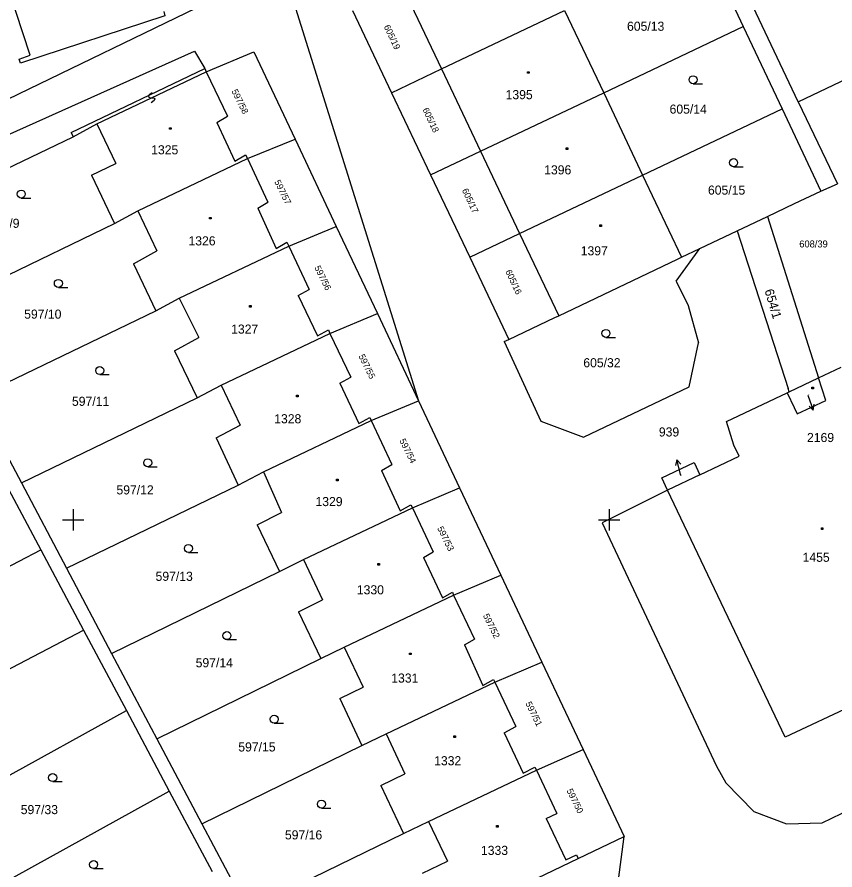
# Model space of a CAD drawing. Extents: x -493648 to -493033, y -1127718 to -1127026.
# Drawn here: x -493205.2 to -493128.9, y -1127182.7 to -1127103.1 of the extents above; entities that cross this region are included whole.
import ezdxf

# ---------------------------------------------------------------- set-up
doc = ezdxf.new("R2010")
doc.units = 0
doc.layers.add('katastrální mapa', color=7, linetype='Continuous')
doc.layers.add('síť', color=7, linetype='Continuous')

msp = doc.modelspace()

# ---------------------------------------------------------------- linework, layer by layer
at = {"layer": 'katastrální mapa'}
for p, q in [((-493189.34, -1127070.04), (-493167.78, -1127138.87)), ((-493141.11, -1127096.24), (-493137.49, -1127103.93)), ((-493169.28, -1127100.21), (-493165.63, -1127107.89)), ((-493220.46, -1127117.66), (-493186.04, -1127100.98)), ((-493132.35, -1127110.95), (-493136.84, -1127101.5)), ((-493173.95, -1127102.43), (-493170.3, -1127110.11)), ((-493165.63, -1127107.89), (-493154.16, -1127102.44)), ((-493154.16, -1127102.44), (-493150.51, -1127110.12)), ((-493132.35, -1127110.95), (-493116.05, -1127103.21)), ((-493150.51, -1127110.12), (-493137.49, -1127103.93)), ((-493137.49, -1127103.93), (-493133.87, -1127111.62)), ((-493218.92, -1127119.76), (-493188.68, -1127106.24)), ((-493188.68, -1127106.24), (-493187.73, -1127107.85)), ((-493187.59, -1127108.15), (-493183.14, -1127106.31)), ((-493183.14, -1127106.31), (-493179.3, -1127114.45)), ((-493200.2, -1127113.82), (-493187.73, -1127107.85)), ((-493197.79, -1127113.01), (-493187.59, -1127108.15)), ((-493187.73, -1127107.85), (-493187.59, -1127108.15)), ((-493187.59, -1127108.15), (-493185.62, -1127112.31)), ((-493170.3, -1127110.11), (-493165.63, -1127107.89)), ((-493165.63, -1127107.89), (-493161.99, -1127115.57)), ((-493157.61, -1127108.15), (-493157.46, -1127108.15)), ((-493157.61, -1127108.3), (-493157.61, -1127108.15)), ((-493157.46, -1127108.3), (-493157.61, -1127108.3)), ((-493157.46, -1127108.15), (-493157.46, -1127108.3)), ((-493142.17, -1127109.28), (-493141.29, -1127109.28)), ((-493192.93, -1127110.31), (-493192.98, -1127110.44)), ((-493192.98, -1127110.44), (-493192.94, -1127110.53)), ((-493192.94, -1127110.53), (-493192.8, -1127110.58)), ((-493192.64, -1127110.11), (-493192.93, -1127110.31)), ((-493192.8, -1127110.58), (-493192.58, -1127110.58)), ((-493192.45, -1127110.85), (-493192.74, -1127111.05)), ((-493192.58, -1127110.58), (-493192.44, -1127110.63)), ((-493192.4, -1127110.72), (-493192.45, -1127110.85)), ((-493192.44, -1127110.63), (-493192.4, -1127110.72)), ((-493170.3, -1127110.11), (-493166.66, -1127117.79)), ((-493161.99, -1127115.57), (-493150.51, -1127110.12)), ((-493150.51, -1127110.12), (-493146.88, -1127117.8)), ((-493146.88, -1127117.8), (-493133.87, -1127111.62)), ((-493133.87, -1127111.62), (-493130.25, -1127119.31)), ((-493132.35, -1127110.95), (-493128.69, -1127118.63)), ((-493186.6, -1127112.9), (-493185.62, -1127112.31)), ((-493200.01, -1127114.22), (-493197.79, -1127113.01)), ((-493197.79, -1127113.01), (-493196.03, -1127116.73)), ((-493186.6, -1127112.9), (-493184.91, -1127116.52)), ((-493200.2, -1127113.82), (-493200.01, -1127114.22)), ((-493191.02, -1127113.38), (-493190.87, -1127113.38)), ((-493191.02, -1127113.53), (-493191.02, -1127113.38)), ((-493190.87, -1127113.53), (-493191.02, -1127113.53)), ((-493190.87, -1127113.38), (-493190.87, -1127113.53)), ((-493217.49, -1127122.64), (-493200.01, -1127114.22)), ((-493183.75, -1127116.27), (-493179.3, -1127114.45)), ((-493179.3, -1127114.45), (-493175.46, -1127122.59)), ((-493166.66, -1127117.79), (-493161.99, -1127115.57)), ((-493161.99, -1127115.57), (-493158.35, -1127123.25)), ((-493154.01, -1127115.26), (-493153.86, -1127115.26)), ((-493154.01, -1127115.41), (-493154.01, -1127115.26)), ((-493153.86, -1127115.41), (-493154.01, -1127115.41)), ((-493153.86, -1127115.26), (-493153.86, -1127115.41)), ((-493193.97, -1127121.13), (-493183.75, -1127116.27)), ((-493184.91, -1127116.52), (-493183.92, -1127115.92)), ((-493183.92, -1127115.92), (-493183.75, -1127116.27)), ((-493183.75, -1127116.27), (-493181.84, -1127120.33)), ((-493198.31, -1127117.81), (-493196.03, -1127116.73)), ((-493138.39, -1127117.02), (-493137.51, -1127117.02)), ((-493198.31, -1127117.81), (-493196.16, -1127122.34)), ((-493166.66, -1127117.79), (-493163.01, -1127125.46)), ((-493158.35, -1127123.25), (-493146.88, -1127117.8)), ((-493146.88, -1127117.8), (-493143.24, -1127125.48)), ((-493130.25, -1127119.31), (-493128.69, -1127118.63)), ((-493132.7, -1127120.47), (-493130.25, -1127119.31)), ((-493204.85, -1127119.95), (-493203.97, -1127119.95)), ((-493182.78, -1127120.9), (-493181.84, -1127120.33)), ((-493196.16, -1127122.34), (-493193.97, -1127121.13)), ((-493193.97, -1127121.13), (-493192.19, -1127124.88)), ((-493182.78, -1127120.9), (-493181.08, -1127124.66)), ((-493135.23, -1127121.67), (-493132.7, -1127120.47)), ((-493187.29, -1127121.75), (-493187.14, -1127121.75)), ((-493187.29, -1127121.9), (-493187.29, -1127121.75)), ((-493187.14, -1127121.9), (-493187.29, -1127121.9)), ((-493187.14, -1127121.75), (-493187.14, -1127121.9)), ((-493138.06, -1127123.02), (-493135.23, -1127121.67)), ((-493135.23, -1127121.67), (-493130.46, -1127136.74)), ((-493213.27, -1127130.61), (-493196.16, -1127122.34)), ((-493179.9, -1127124.43), (-493175.46, -1127122.59)), ((-493175.46, -1127122.59), (-493171.62, -1127130.73)), ((-493150.86, -1127122.46), (-493150.71, -1127122.46)), ((-493150.86, -1127122.61), (-493150.86, -1127122.46)), ((-493150.71, -1127122.61), (-493150.86, -1127122.61)), ((-493150.71, -1127122.46), (-493150.71, -1127122.61)), ((-493163.01, -1127125.46), (-493158.35, -1127123.25)), ((-493158.35, -1127123.25), (-493154.7, -1127130.93)), ((-493141.54, -1127124.67), (-493138.06, -1127123.02)), ((-493138.06, -1127123.02), (-493133.29, -1127137.74)), ((-493181.08, -1127124.66), (-493180.07, -1127124.07)), ((-493180.07, -1127124.07), (-493179.9, -1127124.43)), ((-493194.39, -1127126.08), (-493192.19, -1127124.88)), ((-493190.11, -1127129.3), (-493179.9, -1127124.43)), ((-493179.9, -1127124.43), (-493177.98, -1127128.48)), ((-493143.76, -1127127.7), (-493141.54, -1127124.67)), ((-493143.24, -1127125.48), (-493141.54, -1127124.67)), ((-493163.01, -1127125.46), (-493159.36, -1127133.14)), ((-493154.7, -1127130.93), (-493143.61, -1127125.66)), ((-493143.61, -1127125.66), (-493143.24, -1127125.48)), ((-493194.39, -1127126.08), (-493192.3, -1127130.49)), ((-493201.39, -1127128.29), (-493200.51, -1127128.29)), ((-493143.76, -1127127.7), (-493142.64, -1127129.99)), ((-493179, -1127129.06), (-493177.98, -1127128.48)), ((-493179, -1127129.06), (-493177.21, -1127132.82)), ((-493192.3, -1127130.49), (-493190.11, -1127129.3)), ((-493190.11, -1127129.3), (-493188.27, -1127132.98)), ((-493183.55, -1127129.99), (-493183.4, -1127129.99)), ((-493183.55, -1127130.14), (-493183.55, -1127129.99)), ((-493183.4, -1127129.99), (-493183.4, -1127130.14)), ((-493142.64, -1127129.99), (-493141.65, -1127133.46)), ((-493209.06, -1127138.57), (-493192.3, -1127130.49)), ((-493183.4, -1127130.14), (-493183.55, -1127130.14)), ((-493176.05, -1127132.58), (-493171.62, -1127130.73)), ((-493171.62, -1127130.73), (-493167.78, -1127138.87)), ((-493159.36, -1127133.14), (-493155.07, -1127131.1)), ((-493155.07, -1127131.1), (-493154.7, -1127130.93)), ((-493177.21, -1127132.82), (-493176.2, -1127132.25)), ((-493176.2, -1127132.25), (-493176.05, -1127132.58)), ((-493190.54, -1127134.2), (-493188.27, -1127132.98)), ((-493186.21, -1127137.42), (-493176.05, -1127132.58)), ((-493176.05, -1127132.58), (-493174.11, -1127136.68)), ((-493159.79, -1127133.35), (-493159.36, -1127133.14)), ((-493150.3, -1127132.96), (-493149.42, -1127132.96)), ((-493159.79, -1127133.35), (-493156.37, -1127140.78)), ((-493142.53, -1127137.56), (-493141.65, -1127133.46)), ((-493190.54, -1127134.2), (-493188.45, -1127138.6)), ((-493130.46, -1127136.74), (-493128.35, -1127135.75)), ((-493197.53, -1127136.43), (-493196.65, -1127136.43)), ((-493175.12, -1127137.23), (-493174.11, -1127136.68)), ((-493133.2, -1127138.04), (-493130.46, -1127136.74)), ((-493129.79, -1127138.85), (-493130.46, -1127136.74)), ((-493188.45, -1127138.6), (-493186.21, -1127137.42)), ((-493186.21, -1127137.42), (-493184.43, -1127141.16)), ((-493175.12, -1127137.23), (-493173.37, -1127141)), ((-493152.38, -1127142.26), (-493142.53, -1127137.56)), ((-493133.2, -1127138.04), (-493133.29, -1127137.74)), ((-493131.09, -1127137.61), (-493130.94, -1127137.61)), ((-493131.09, -1127137.76), (-493131.09, -1127137.61)), ((-493130.94, -1127137.76), (-493131.09, -1127137.76)), ((-493130.94, -1127137.61), (-493130.94, -1127137.76)), ((-493209.06, -1127138.57), (-493204.84, -1127146.54)), ((-493204.84, -1127146.54), (-493188.45, -1127138.6)), ((-493179.17, -1127138.36), (-493179.02, -1127138.36)), ((-493179.17, -1127138.51), (-493179.17, -1127138.36)), ((-493179.02, -1127138.51), (-493179.17, -1127138.51)), ((-493179.02, -1127138.36), (-493179.02, -1127138.51)), ((-493139.04, -1127140.8), (-493133.39, -1127138.12)), ((-493133.39, -1127138.12), (-493133.2, -1127138.04)), ((-493133.39, -1127138.12), (-493132.73, -1127139.5)), ((-493131.46, -1127138.35), (-493130.95, -1127139.76)), ((-493172.2, -1127140.73), (-493167.78, -1127138.87)), ((-493167.78, -1127138.87), (-493163.95, -1127147.01)), ((-493132.73, -1127139.5), (-493132.45, -1127140.11)), ((-493132.45, -1127140.11), (-493129.79, -1127138.85)), ((-493130.95, -1127139.76), (-493131.35, -1127139.38)), ((-493130.95, -1127139.76), (-493130.88, -1127139.2)), ((-493182.24, -1127145.51), (-493172.2, -1127140.73)), ((-493173.37, -1127141), (-493172.33, -1127140.45)), ((-493172.33, -1127140.45), (-493172.2, -1127140.73)), ((-493172.2, -1127140.73), (-493170.27, -1127144.82)), ((-493156.37, -1127140.78), (-493152.38, -1127142.26)), ((-493138.35, -1127143.01), (-493139.04, -1127140.8)), ((-493186.68, -1127142.34), (-493184.43, -1127141.16)), ((-493186.68, -1127142.34), (-493184.6, -1127146.74)), ((-493137.86, -1127144.05), (-493138.35, -1127143.01)), ((-493141.53, -1127145.78), (-493137.86, -1127144.05)), ((-493207.23, -1127144.94), (-493203.03, -1127152.8)), ((-493193.05, -1127145.04), (-493192.17, -1127145.04)), ((-493171.23, -1127145.4), (-493170.27, -1127144.82)), ((-493145.09, -1127146.08), (-493142.06, -1127144.65)), ((-493143.68, -1127144.39), (-493143.8, -1127144.93)), ((-493143.31, -1127145.84), (-493143.68, -1127144.39)), ((-493143.68, -1127144.39), (-493143.32, -1127144.81)), ((-493142.06, -1127144.65), (-493141.53, -1127145.78)), ((-493184.6, -1127146.74), (-493182.24, -1127145.51)), ((-493182.24, -1127145.51), (-493180.57, -1127149.32)), ((-493171.23, -1127145.4), (-493169.49, -1127149.16)), ((-493141.53, -1127145.78), (-493144.56, -1127147.22)), ((-493204.84, -1127146.54), (-493200.63, -1127154.5)), ((-493175.44, -1127146.21), (-493175.29, -1127146.21)), ((-493175.44, -1127146.36), (-493175.44, -1127146.21)), ((-493175.29, -1127146.36), (-493175.44, -1127146.36)), ((-493175.29, -1127146.21), (-493175.29, -1127146.36)), ((-493144.56, -1127147.22), (-493145.09, -1127146.08)), ((-493200.63, -1127154.5), (-493184.6, -1127146.74)), ((-493168.35, -1127148.87), (-493163.95, -1127147.01)), ((-493163.95, -1127147.01), (-493160.11, -1127155.15)), ((-493144.56, -1127147.22), (-493150.66, -1127150.28)), ((-493133.58, -1127170.28), (-493144.56, -1127147.22)), ((-493178.51, -1127153.71), (-493168.35, -1127148.87)), ((-493169.49, -1127149.16), (-493168.49, -1127148.58)), ((-493168.49, -1127148.58), (-493168.35, -1127148.87)), ((-493168.35, -1127148.87), (-493166.41, -1127152.99)), ((-493182.84, -1127150.45), (-493180.57, -1127149.32)), ((-493182.84, -1127150.45), (-493180.76, -1127154.82)), ((-493150.66, -1127150.28), (-493139.97, -1127172.98)), ((-493130.2, -1127150.73), (-493130.05, -1127150.73)), ((-493130.2, -1127150.88), (-493130.2, -1127150.73)), ((-493130.05, -1127150.88), (-493130.2, -1127150.88)), ((-493130.05, -1127150.73), (-493130.05, -1127150.88)), ((-493222.65, -1127163.04), (-493203.03, -1127152.8)), ((-493203.03, -1127152.8), (-493199.04, -1127160.3)), ((-493189.25, -1127153.04), (-493188.37, -1127153.04)), ((-493167.32, -1127153.52), (-493166.41, -1127152.99)), ((-493180.76, -1127154.82), (-493178.51, -1127153.71)), ((-493178.51, -1127153.71), (-493176.74, -1127157.45)), ((-493167.32, -1127153.52), (-493165.55, -1127157.27)), ((-493200.63, -1127154.5), (-493196.42, -1127162.46)), ((-493171.58, -1127154.06), (-493171.43, -1127154.06)), ((-493171.58, -1127154.21), (-493171.58, -1127154.06)), ((-493171.43, -1127154.21), (-493171.58, -1127154.21)), ((-493171.43, -1127154.06), (-493171.43, -1127154.21)), ((-493196.42, -1127162.46), (-493180.76, -1127154.82)), ((-493164.51, -1127157.01), (-493160.11, -1127155.15)), ((-493160.11, -1127155.15), (-493156.27, -1127163.29)), ((-493174.73, -1127161.88), (-493164.51, -1127157.01)), ((-493165.55, -1127157.27), (-493164.63, -1127156.75)), ((-493164.63, -1127156.75), (-493164.51, -1127157.01)), ((-493164.51, -1127157.01), (-493162.56, -1127161.14)), ((-493178.99, -1127158.57), (-493176.74, -1127157.45)), ((-493178.99, -1127158.57), (-493176.91, -1127162.95)), ((-493218.41, -1127170.42), (-493199.04, -1127160.3)), ((-493199.04, -1127160.3), (-493195.04, -1127167.8)), ((-493185.66, -1127161.18), (-493184.78, -1127161.18)), ((-493163.51, -1127161.67), (-493162.56, -1127161.14)), ((-493163.51, -1127161.67), (-493161.78, -1127165.46)), ((-493196.42, -1127162.46), (-493192.2, -1127170.43)), ((-493176.91, -1127162.95), (-493174.73, -1127161.88)), ((-493174.73, -1127161.88), (-493172.94, -1127165.6)), ((-493168.62, -1127162.43), (-493168.47, -1127162.43)), ((-493168.62, -1127162.58), (-493168.62, -1127162.43)), ((-493168.47, -1127162.58), (-493168.62, -1127162.58)), ((-493168.47, -1127162.43), (-493168.47, -1127162.58)), ((-493115.95, -1127161.97), (-493133.58, -1127170.28)), ((-493192.2, -1127170.43), (-493176.91, -1127162.95)), ((-493160.67, -1127165.15), (-493156.27, -1127163.29)), ((-493156.27, -1127163.29), (-493152.43, -1127171.43)), ((-493161.78, -1127165.46), (-493160.78, -1127164.91)), ((-493160.78, -1127164.91), (-493160.67, -1127165.15)), ((-493175.14, -1127166.68), (-493172.94, -1127165.6)), ((-493170.81, -1127169.98), (-493160.67, -1127165.15)), ((-493160.67, -1127165.15), (-493158.71, -1127169.3)), ((-493175.14, -1127166.68), (-493173.07, -1127171.06)), ((-493213.92, -1127178.24), (-493195.04, -1127167.8)), ((-493195.04, -1127167.8), (-493191.04, -1127175.31)), ((-493181.25, -1127168.98), (-493180.37, -1127168.98)), ((-493159.78, -1127169.88), (-493158.71, -1127169.3)), ((-493192.2, -1127170.43), (-493187.99, -1127178.39)), ((-493173.07, -1127171.06), (-493170.81, -1127169.98)), ((-493170.81, -1127169.98), (-493169.05, -1127173.7)), ((-493164.5, -1127170.16), (-493164.35, -1127170.16)), ((-493164.5, -1127170.31), (-493164.5, -1127170.16)), ((-493164.35, -1127170.31), (-493164.5, -1127170.31)), ((-493164.35, -1127170.16), (-493164.35, -1127170.31)), ((-493159.78, -1127169.88), (-493158.03, -1127173.65)), ((-493187.99, -1127178.39), (-493173.07, -1127171.06)), ((-493156.79, -1127173.36), (-493152.43, -1127171.43)), ((-493152.43, -1127171.43), (-493148.59, -1127179.57)), ((-493139.97, -1127172.98), (-493139.1, -1127174.55)), ((-493171.3, -1127174.79), (-493169.05, -1127173.7)), ((-493166.85, -1127178.15), (-493156.79, -1127173.36)), ((-493158.03, -1127173.65), (-493156.92, -1127173.07)), ((-493156.92, -1127173.07), (-493156.79, -1127173.36)), ((-493156.79, -1127173.36), (-493154.87, -1127177.41)), ((-493201.92, -1127174.43), (-493201.04, -1127174.43)), ((-493139.1, -1127174.55), (-493136.49, -1127177.23)), ((-493209.67, -1127185.62), (-493191.04, -1127175.31)), ((-493191.04, -1127175.31), (-493187.04, -1127182.81)), ((-493171.3, -1127174.79), (-493169.18, -1127179.27)), ((-493176.84, -1127176.91), (-493175.96, -1127176.91)), ((-493130.11, -1127178.29), (-493127.41, -1127176.97)), ((-493155.87, -1127177.88), (-493154.87, -1127177.41)), ((-493136.49, -1127177.23), (-493133.46, -1127178.38)), ((-493187.99, -1127178.39), (-493183.77, -1127186.36)), ((-493169.18, -1127179.27), (-493166.85, -1127178.15)), ((-493166.85, -1127178.15), (-493165.08, -1127181.86)), ((-493160.51, -1127178.53), (-493160.36, -1127178.53)), ((-493160.51, -1127178.68), (-493160.51, -1127178.53)), ((-493160.36, -1127178.53), (-493160.36, -1127178.68)), ((-493155.87, -1127177.88), (-493154.05, -1127181.73)), ((-493133.46, -1127178.38), (-493130.11, -1127178.29)), ((-493183.77, -1127186.36), (-493169.18, -1127179.27)), ((-493160.36, -1127178.68), (-493160.51, -1127178.68)), ((-493152.88, -1127181.62), (-493148.59, -1127179.57)), ((-493149.22, -1127184.31), (-493148.59, -1127179.57)), ((-493165.27, -1127187.52), (-493152.88, -1127181.62)), ((-493154.05, -1127181.73), (-493153.06, -1127181.26)), ((-493153.06, -1127181.26), (-493152.88, -1127181.62)), ((-493198.1, -1127182.55), (-493197.22, -1127182.55)), ((-493167.42, -1127182.97), (-493165.08, -1127181.86))]:
    msp.add_line(p, q, dxfattribs=at)
for points in [[(-493205.05, -1127106.97), (-493204.01, -1127106.62), (-493206.67, -1127098.53)], [(-493191.56, -1127102.53), (-493191.45, -1127102.93), (-493204.92, -1127107.35), (-493205.05, -1127106.97)]]:
    msp.add_lwpolyline(points, dxfattribs=at)
for centre in [(-493142.17, -1127108.905), (-493138.39, -1127116.645), (-493204.85, -1127119.575), (-493201.39, -1127127.915), (-493150.3, -1127132.585), (-493197.53, -1127136.055), (-493193.05, -1127144.665), (-493189.25, -1127152.665), (-493185.66, -1127160.805), (-493181.25, -1127168.605), (-493201.92, -1127174.055), (-493176.84, -1127176.535), (-493198.1, -1127182.175)]:
    msp.add_circle(centre, 0.375, dxfattribs=at)
at = {"layer": 'síť'}
for p, q in [((-493200, -1127149), (-493200, -1127151)), ((-493150, -1127149), (-493150, -1127151)), ((-493201, -1127150), (-493199, -1127150)), ((-493151, -1127150), (-493149, -1127150))]:
    msp.add_line(p, q, dxfattribs=at)

# ---------------------------------------------------------------- texts
at = {"layer": 'katastrální mapa'}
for s, height, p in [('605/13', 0.849996, (-493148.33, -1127104.33)), ('1395', 0.849996, (-493159.66, -1127110.72)), ('605/14', 0.849996, (-493144.36, -1127112.07)), ('1325', 0.849996, (-493192.73, -1127115.87)), ('1396', 0.849996, (-493156.06, -1127117.74)), ('605/15', 0.849996, (-493140.78, -1127119.63)), ('597/9', 0.849996, (-493207.86, -1127122.73)), ('1326', 0.849996, (-493189.25, -1127124.37)), ('608/39', 0.649998, (-493132.26, -1127124.56)), ('1397', 0.849996, (-493152.65, -1127125.3)), ('597/10', 0.849996, (-493204.58, -1127131.21)), ('1327', 0.849996, (-493185.27, -1127132.61)), ('605/32', 0.849996, (-493152.41, -1127135.75)), ('597/11', 0.849996, (-493200.12, -1127139.35)), ('2169', 0.049998, (-493131.46, -1127138.35)), ('1328', 0.849996, (-493181.25, -1127140.98)), ('939', 0.849996, (-493145.36, -1127142.21)), ('2169', 0.849996, (-493131.54, -1127142.73)), ('939', 0.049998, (-493143.31, -1127145.84)), ('597/12', 0.849996, (-493195.97, -1127147.62)), ('1329', 0.849996, (-493177.4, -1127148.71)), ('1455', 0.849996, (-493131.95, -1127153.91)), ('597/13', 0.849996, (-493192.32, -1127155.69)), ('1330', 0.849996, (-493173.54, -1127156.95)), ('597/14', 0.849996, (-493188.58, -1127163.76)), ('1331', 0.849996, (-493170.33, -1127165.19)), ('597/15', 0.849996, (-493184.6, -1127171.62)), ('1332', 0.849996, (-493166.33, -1127172.91)), ('597/33', 0.849996, (-493204.9, -1127177.47)), ('597/16', 0.849996, (-493180.25, -1127179.83)), ('1333', 0.849996, (-493161.96, -1127181.28))]:
    msp.add_text(s, height=height, dxfattribs=at).set_placement(p)
for s, height, rotation, p in [('605/19', 0.599994, 295.1279972, (-493171.04, -1127103.94)), ('597/58', 0.599994, 296.3879972, (-493185.25, -1127109.97)), ('605/18', 0.599994, 295.1279972, (-493167.43, -1127111.68)), ('597/57', 0.599994, 296.3879972, (-493181.26, -1127118.43)), ('605/17', 0.599994, 295.1279972, (-493163.75, -1127119.22)), ('597/56', 0.599994, 296.3879972, (-493177.52, -1127126.44)), ('605/16', 0.599994, 295.1279972, (-493159.7, -1127126.8)), ('654/1', 0.849996, 286.5959972, (-493135.51, -1127128.58)), ('597/55', 0.599994, 296.3879972, (-493173.4, -1127134.71)), ('597/54', 0.599994, 296.3879972, (-493169.59, -1127142.59)), ('597/53', 0.599994, 296.3879972, (-493166.06, -1127150.78)), ('597/52', 0.599994, 296.3879972, (-493161.79, -1127158.93)), ('597/51', 0.599994, 296.3879972, (-493157.83, -1127167.14)), ('597/50', 0.599994, 296.3879972, (-493153.99, -1127175.27))]:
    msp.add_text(s, height=height, rotation=rotation, dxfattribs=at).set_placement(p)

doc.saveas('drawing.dxf')
